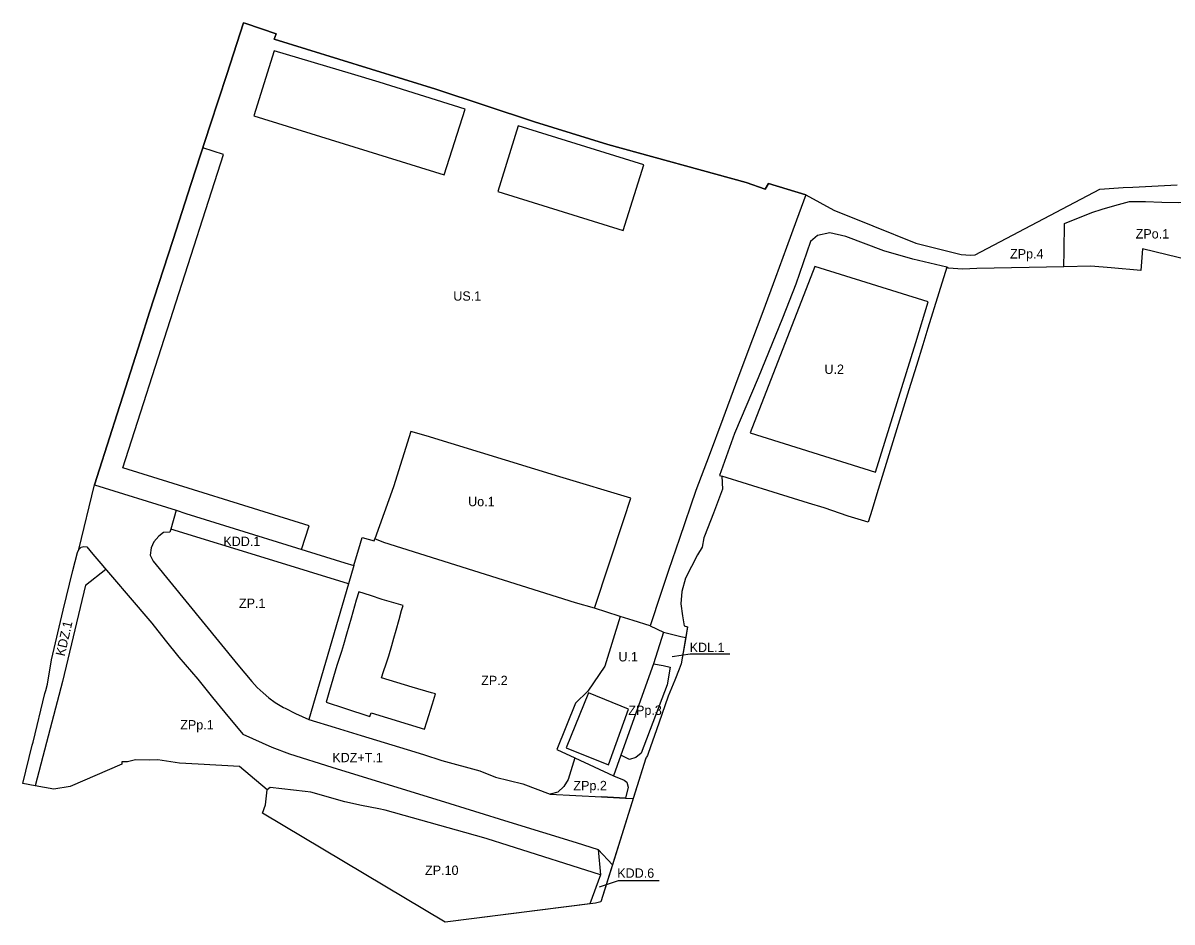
# Model space of a CAD drawing. Extents: x 7421682 to 7423374, y 5548937 to 5549733.
# Drawn here: x 7421682 to 7422295, y 5549198 to 5549678 of the extents above; entities that cross this region are included whole.
import ezdxf

# ---------------------------------------------------------------- set-up
doc = ezdxf.new("R2010")
doc.units = 0
for name, color, linetype in [('LIN_Granica_planu', 7, 'Continuous'), ('LIN_Linia Zabudowy Nieprzekraczalna', 7, 'Continuous'), ('LIN_Linie Rozgraniczajace', 7, 'Continuous'), ('TXT_Oznaczenia Przeznaczenia', 7, 'Continuous')]:
    doc.layers.add(name, color=color, linetype=linetype)

msp = doc.modelspace()

# ---------------------------------------------------------------- linework, layer by layer
at = {"layer": 'LIN_Granica_planu'}
msp.add_lwpolyline([(7422304.34, 5549550.82), (7422278.84, 5549557.04), (7422277.91, 5549545.5), (7422262.08, 5549546.93), (7422251.27, 5549547.91), (7422236.83, 5549547.59), (7422190.5, 5549546.57), (7422183.02, 5549546.21), (7422175.25, 5549546.85), (7422174.61, 5549547.38), (7422170.37, 5549533.68), (7422164.48, 5549514.76), (7422161.77, 5549505.95), (7422158.37, 5549494.92), (7422154.33, 5549481.87), (7422147.18, 5549458.85), (7422137.19, 5549426.41), (7422134.83, 5549418.2), (7422132.71, 5549411.4), (7422122, 5549414.57), (7422109.19, 5549418.97), (7422100.92, 5549421.51), (7422081.94, 5549427.43), (7422054.62, 5549435.85), (7422055.01, 5549429.07), (7422050.15, 5549416.25), (7422045.51, 5549403.99), (7422045.14, 5549403.05), (7422044.15, 5549397.98), (7422041.62, 5549393.93), (7422035.37, 5549381.46), (7422033.4, 5549374.4), (7422032.73, 5549367.82), (7422033.78, 5549361.38), (7422034.51, 5549356.1), (7422036.42, 5549355.66), (7422033.04, 5549335.91), (7422031.88, 5549332.98), (7422029.55, 5549327.08), (7422026.15, 5549318.61), (7422021.09, 5549304.32), (7422015.34, 5549288.01), (7422015.18, 5549287.5), (7422014.99, 5549287), (7422014.77, 5549286.52), (7422014.51, 5549286.05), (7422014.22, 5549285.61), (7422014.22, 5549285.61), (7421990.18, 5549208.93), (7421987.32, 5549208.37), (7421907.22, 5549198.23), (7421809.86, 5549256.27), (7421811.56, 5549260.78), (7421812.41, 5549268.71), (7421803.32, 5549276.43), (7421797.73, 5549281.18), (7421775.55, 5549282.39), (7421765.66, 5549282.89), (7421754.1, 5549284.77), (7421749.73, 5549284.51), (7421742.31, 5549284.67), (7421737.89, 5549283.7), (7421735.04, 5549283.56), (7421734.95, 5549282.42), (7421707.48, 5549270.46), (7421698.74, 5549268.98), (7421688.74, 5549270.86), (7421682.28, 5549272.07), (7421687.22, 5549292.43), (7421687.67, 5549294.06), (7421694.01, 5549320.11), (7421694.43, 5549321.74), (7421695.29, 5549325.07), (7421697.49, 5549338.02), (7421703.73, 5549364.44), (7421708.87, 5549385.54), (7421711.25, 5549395.29), (7421711.97, 5549396.81), (7421720.46, 5549431.35), (7421729.75, 5549460.78), (7421731.02, 5549464.79), (7421736.83, 5549483.07), (7421744.88, 5549507.99), (7421749.78, 5549523.35), (7421762.14, 5549561.56), (7421771.9, 5549592), (7421782.1, 5549623.07), (7421790.83, 5549649.96), (7421799.83, 5549677.51), (7421801.03, 5549677.15), (7421817.17, 5549671.71), (7421816.16, 5549668.9), (7421902.24, 5549642.26), (7421954.88, 5549624.79), (7421993.9, 5549612.76), (7422067.58, 5549592.53), (7422077.73, 5549588.84), (7422079.51, 5549591.91), (7422099.45, 5549585.93), (7422114.33, 5549577.76), (7422135.18, 5549569.45), (7422158.05, 5549560.04), (7422182.18, 5549554.02), (7422187.2, 5549553.79), (7422189.62, 5549553.99), (7422256.12, 5549588.87), (7422268.48, 5549589.78), (7422273.65, 5549590.03), (7422297.21, 5549591.24)], dxfattribs=at)
at = {"layer": 'LIN_Linia Zabudowy Nieprzekraczalna'}
for points in [[(7421917.93, 5549631.49), (7421872, 5549645.99), (7421857.39, 5549650.35), (7421816.07, 5549662.57), (7421805.37, 5549628.03), (7421906.67, 5549596.56)], [(7421935.32, 5549587.66), (7422002.17, 5549566.9), (7422013.03, 5549601.86), (7421946.2, 5549622.68)], [(7422104.19, 5549547.73), (7422069.76, 5549458.97), (7422136.59, 5549438.04), (7422157.95, 5549507.13), (7422164.66, 5549528.8)], [(7421861.16, 5549374.24), (7421859.83, 5549369.81), (7421857.16, 5549360.24), (7421854.72, 5549351.71), (7421853, 5549345.93), (7421851.94, 5549342.49), (7421849.52, 5549334.93), (7421845.69, 5549321.69), (7421843.81, 5549315.5), (7421853.68, 5549312.19), (7421867.12, 5549307.73), (7421867.78, 5549309.74), (7421896.23, 5549301.08), (7421897.47, 5549305), (7421900.43, 5549314.57), (7421902.13, 5549319.83), (7421900.03, 5549320.41), (7421889.72, 5549323.45), (7421873.25, 5549328.38), (7421874.43, 5549331.86), (7421875.79, 5549335.94), (7421877.16, 5549340.06), (7421878.77, 5549345.68), (7421879.92, 5549349.61), (7421881.18, 5549353.9), (7421882.72, 5549359.52), (7421884.06, 5549364.33), (7421884.8, 5549367.01), (7421873.75, 5549370.24), (7421867.52, 5549372.27)], [(7421971.74, 5549291.12), (7421994.35, 5549281.98), (7422004.96, 5549311.78), (7421983.54, 5549320.43)]]:
    msp.add_lwpolyline(points, close=True, dxfattribs=at)
msp.add_lwpolyline([(7421830.72, 5549396.89), (7421834.75, 5549409.4), (7421735.53, 5549440.4), (7421789.05, 5549607.41), (7421778.11, 5549610.91)], dxfattribs=at)
at = {"layer": 'LIN_Linie Rozgraniczajace'}
for p, q in [((7421720.46, 5549431.35), (7421763.84, 5549417.79)), ((7421763.84, 5549417.79), (7421761, 5549407.75)), ((7421715.56, 5549377.76), (7421726.37, 5549386.36)), ((7421855.71, 5549378.6), (7421834.68, 5549306.21)), ((7422023.5, 5549352.73), (7422018.19, 5549335.94)), ((7422018.19, 5549335.94), (7422000.79, 5549287.1)), ((7421976.42, 5549285.7), (7421996.92, 5549276.23)), ((7422000.79, 5549287.1), (7421996.92, 5549276.23)), ((7422003.33, 5549264.3), (7421990.51, 5549264.96)), ((7422003.33, 5549264.3), (7422007.47, 5549264.09))]:
    msp.add_line(p, q, dxfattribs=at)
for points in [[(7422099.45, 5549585.93), (7422079.51, 5549591.91), (7422077.73, 5549588.84), (7422067.58, 5549592.53), (7421993.9, 5549612.76), (7421954.88, 5549624.79), (7421902.24, 5549642.26), (7421816.16, 5549668.9), (7421817.17, 5549671.71), (7421801.03, 5549677.15), (7421799.83, 5549677.51), (7421790.83, 5549649.96), (7421782.1, 5549623.07), (7421771.9, 5549592), (7421762.14, 5549561.56), (7421749.78, 5549523.35), (7421744.88, 5549507.99), (7421736.83, 5549483.07), (7421731.02, 5549464.79), (7421729.75, 5549460.78), (7421720.46, 5549431.35)], [(7422099.45, 5549585.93), (7422094.5, 5549572.39), (7422089.14, 5549557.84), (7422083.3, 5549541.91), (7422076.5, 5549523.6), (7422067.92, 5549501.01), (7422061.88, 5549484.77), (7422055.17, 5549466.49), (7422047.85, 5549446.93), (7422040.89, 5549428.26), (7422032.07, 5549402.74), (7422026.31, 5549385.64), (7422022.22, 5549373.3), (7422016.43, 5549356.09)], [(7422099.45, 5549585.93), (7422114.33, 5549577.76), (7422135.18, 5549569.45), (7422158.05, 5549560.04), (7422182.18, 5549554.02), (7422187.2, 5549553.79), (7422189.62, 5549553.99), (7422256.12, 5549588.87), (7422268.48, 5549589.78), (7422273.65, 5549590.03), (7422297.21, 5549591.24)], [(7422236.83, 5549547.59), (7422236.99, 5549555.99), (7422237.25, 5549570.61), (7422251.9, 5549576.52), (7422257.36, 5549578.29), (7422264.07, 5549580.24), (7422271.83, 5549582.26), (7422280.46, 5549582.28), (7422289.17, 5549582.03), (7422297.88, 5549581.77), (7422314.66, 5549582.37), (7422325.3, 5549583.85), (7422332.58, 5549584.79), (7422341.22, 5549583.27), (7422337.46, 5549560.07), (7422333.61, 5549542.2)], [(7422174.61, 5549547.38), (7422156.47, 5549551.56), (7422140.94, 5549556.12), (7422120.77, 5549563.73), (7422112.27, 5549565.6), (7422105.68, 5549564.28), (7422101.91, 5549561.03), (7422094.07, 5549538.28), (7422087.06, 5549520.17), (7422074.01, 5549488.4), (7422061.47, 5549458.71), (7422053.49, 5549436.19), (7422054.62, 5549435.85)], [(7422333.61, 5549542.2), (7422322.77, 5549545.59), (7422312.18, 5549548.9), (7422304.34, 5549550.82), (7422278.84, 5549557.04), (7422277.91, 5549545.5), (7422262.08, 5549546.93), (7422251.27, 5549547.91), (7422236.83, 5549547.59)], [(7422174.61, 5549547.38), (7422170.37, 5549533.68), (7422164.48, 5549514.76), (7422161.77, 5549505.95), (7422158.37, 5549494.92), (7422154.33, 5549481.87), (7422147.18, 5549458.85), (7422137.19, 5549426.41), (7422134.83, 5549418.2), (7422132.71, 5549411.4), (7422122, 5549414.57), (7422109.19, 5549418.97), (7422100.92, 5549421.51), (7422081.94, 5549427.43), (7422054.62, 5549435.85)], [(7422236.83, 5549547.59), (7422190.5, 5549546.57), (7422183.02, 5549546.21), (7422175.25, 5549546.85), (7422174.61, 5549547.38)], [(7422236.83, 5549547.59), (7422236.83, 5549547.59)], [(7421986.73, 5549365.5), (7422002.43, 5549412.74), (7422006.26, 5549424.12), (7421968.3, 5549435.64), (7421897.12, 5549457.37), (7421888.94, 5549459.78), (7421879.64, 5549430.27), (7421869.71, 5549402.51)], [(7422054.62, 5549435.85), (7422055.01, 5549429.07), (7422050.15, 5549416.25), (7422045.51, 5549403.99), (7422045.14, 5549403.05), (7422044.15, 5549397.98), (7422041.62, 5549393.93), (7422035.37, 5549381.46), (7422033.4, 5549374.4), (7422032.73, 5549367.82), (7422033.78, 5549361.38), (7422034.51, 5549356.1), (7422036.42, 5549355.66), (7422035.44, 5549349.95)], [(7421711.97, 5549396.81), (7421720.46, 5549431.35)], [(7421763.84, 5549417.79), (7421769.05, 5549416.01), (7421853.74, 5549389.75), (7421858.52, 5549388.32)], [(7421761, 5549407.75), (7421760.52, 5549406.03), (7421757.2, 5549405.8), (7421754.64, 5549403.99), (7421752.08, 5549400.93), (7421750.5, 5549397.65), (7421750.12, 5549393.83), (7421751.64, 5549390.54), (7421796.82, 5549335.42), (7421804.21, 5549326.42), (7421807.03, 5549323.33), (7421810.19, 5549320.33), (7421813.29, 5549317.77), (7421816.72, 5549315.25), (7421821.08, 5549312.65), (7421821.94, 5549312.15), (7421827.49, 5549309.34), (7421834.68, 5549306.21)], [(7421855.71, 5549378.6), (7421813.16, 5549391.7), (7421761, 5549407.75)], [(7421858.52, 5549388.32), (7421862.19, 5549400.26), (7421863.04, 5549403.29), (7421869.36, 5549401.37), (7421869.71, 5549402.51)], [(7421986.73, 5549365.5), (7421976.61, 5549368.44), (7421874.55, 5549400.61), (7421869.71, 5549402.51)], [(7421688.74, 5549270.86), (7421682.28, 5549272.07), (7421687.22, 5549292.43), (7421687.67, 5549294.06), (7421694.01, 5549320.11), (7421694.43, 5549321.74), (7421695.29, 5549325.07), (7421697.49, 5549338.02), (7421703.73, 5549364.44), (7421708.87, 5549385.54), (7421711.25, 5549395.29), (7421711.97, 5549396.81)], [(7421711.97, 5549396.81), (7421713.2, 5549397.98), (7421714.7, 5549398.5), (7421716.28, 5549398.25), (7421719.55, 5549394.4)], [(7421719.55, 5549394.4), (7421749.81, 5549358.73)], [(7421858.52, 5549388.32), (7421855.71, 5549378.6)], [(7421715.56, 5549377.76), (7421703.26, 5549326.52)], [(7422000.41, 5549361.16), (7422000.02, 5549361.28), (7421986.73, 5549365.5)], [(7421749.81, 5549358.73), (7421750.85, 5549357.56), (7421758.05, 5549348.51), (7421765.25, 5549339.47), (7421775.37, 5549327.63), (7421781.76, 5549319.79), (7421783.3, 5549317.98), (7421789.92, 5549309.9), (7421799.4, 5549298.33), (7421814.87, 5549291.36), (7421824.29, 5549287.89), (7421846.92, 5549280.79), (7421865.9, 5549274.92), (7421904.55, 5549263.02), (7421941.23, 5549251.71), (7421977.05, 5549240.62), (7421988.8, 5549236.97)], [(7422000.41, 5549361.16), (7421992.38, 5549334.65), (7421983.18, 5549321.22), (7421976.72, 5549314.9), (7421966.78, 5549290.26), (7421976.42, 5549285.7)], [(7422016.43, 5549356.09), (7422007.48, 5549358.91), (7422000.41, 5549361.16)], [(7422016.43, 5549356.09), (7422023.5, 5549352.83), (7422023.5, 5549352.73)], [(7422023.5, 5549352.73), (7422032.88, 5549350.49), (7422035.44, 5549349.95)], [(7422035.44, 5549349.95), (7422033.04, 5549335.91), (7422031.88, 5549332.98), (7422029.55, 5549327.08), (7422026.15, 5549318.61), (7422021.09, 5549304.32), (7422015.34, 5549288.01), (7422015.18, 5549287.5), (7422014.99, 5549287), (7422014.77, 5549286.52), (7422014.51, 5549286.05), (7422014.22, 5549285.61), (7422014.22, 5549285.61), (7422007.47, 5549264.09)], [(7422018.19, 5549335.94), (7422023.38, 5549334.94), (7422027.2, 5549334.06), (7422025.52, 5549324.71), (7422011.63, 5549288.17), (7422008.77, 5549285.91), (7422005.49, 5549284.96), (7422000.79, 5549287.1)], [(7421703.26, 5549326.52), (7421694.74, 5549293.89), (7421688.74, 5549270.86)], [(7421834.68, 5549306.21), (7421848.58, 5549301.97), (7421862.47, 5549297.73), (7421886.91, 5549290.27), (7421895.67, 5549287.47), (7421905.51, 5549284.31), (7421925.72, 5549278.78), (7421934.14, 5549275.47), (7421948.68, 5549271.95), (7421963.21, 5549266.36)], [(7421976.42, 5549285.7), (7421972.78, 5549274.14), (7421970.42, 5549270.46), (7421967.35, 5549267.42), (7421963.21, 5549266.36)], [(7421812.41, 5549268.71), (7421803.32, 5549276.43), (7421797.73, 5549281.18), (7421775.55, 5549282.39), (7421765.66, 5549282.89), (7421754.1, 5549284.77), (7421749.73, 5549284.51), (7421742.31, 5549284.67), (7421737.89, 5549283.7), (7421735.04, 5549283.56), (7421734.95, 5549282.42), (7421707.48, 5549270.46), (7421698.74, 5549268.98), (7421688.74, 5549270.86)], [(7421996.92, 5549276.23), (7422002.55, 5549273.92), (7422004.06, 5549272.75), (7422004.73, 5549270.19), (7422003.33, 5549264.3)], [(7421984.37, 5549208), (7421907.22, 5549198.23), (7421809.86, 5549256.27), (7421811.56, 5549260.78), (7421812.41, 5549268.71)], [(7421989.99, 5549223.41), (7421940.76, 5549238.97), (7421929.69, 5549242.54), (7421927.85, 5549243.14), (7421875.24, 5549257.79), (7421871.85, 5549258.5), (7421862.62, 5549260.3), (7421853.78, 5549262.35), (7421835.63, 5549267.41), (7421832.69, 5549267.83), (7421814.08, 5549269.9), (7421812.41, 5549268.71)], [(7421963.21, 5549266.36), (7421990.51, 5549264.96)], [(7421990.51, 5549264.96), (7422003.33, 5549264.3)], [(7422007.47, 5549264.09), (7421996.4, 5549228.78)], [(7422003.33, 5549264.3), (7422007.47, 5549264.09)], [(7421988.8, 5549236.97), (7421996.4, 5549228.78)], [(7421988.8, 5549236.97), (7421989.99, 5549223.41)], [(7421996.4, 5549228.78), (7421990.18, 5549208.93), (7421987.32, 5549208.37), (7421984.37, 5549208)], [(7421989.99, 5549223.41), (7421984.37, 5549208)]]:
    msp.add_lwpolyline(points, dxfattribs=at)
at = {"layer": 'TXT_Oznaczenia Przeznaczenia'}
for points in [[(7422059, 5549341.04), (7422037.83, 5549341.04), (7422028.23, 5549339.65)], [(7422021.32, 5549220.27), (7421999.34, 5549220.27), (7421989.34, 5549216.87)]]:
    msp.add_lwpolyline(points, dxfattribs=at)

# ---------------------------------------------------------------- texts
for s, p in [('ZPo.1', (7422275.18, 5549562.61)), ('ZPp.4', (7422208.23, 5549551.95)), ('US.1', (7421911.58, 5549529.46)), ('U.2', (7422109.33, 5549490.42)), ('Uo.1', (7421919.48, 5549419.9)), ('KDD.1', (7421789.05, 5549398.66)), ('ZP.1', (7421797.37, 5549365.66)), ('   KDL.1', (7422031.94, 5549342.12)), ('U.1', (7421999.55, 5549337.16)), ('ZP.2', (7421926.42, 5549324.51)), ('ZPp.3', (7422004.85, 5549308.64)), ('ZPp.1', (7421766.06, 5549300.88)), ('KDZ+T.1', (7421847.1, 5549283.42)), ('ZPp.2', (7421975.57, 5549268.48)), ('ZP.10', (7421896.52, 5549223.35)), ('    KDD.6', (7421991.5, 5549221.83))]:
    msp.add_text(s, height=5, dxfattribs=at).set_placement(p)
msp.add_text('KDZ.1', height=5, rotation=77.08003, dxfattribs=at).set_placement((7421704.47, 5549339.63))

doc.saveas('drawing.dxf')
